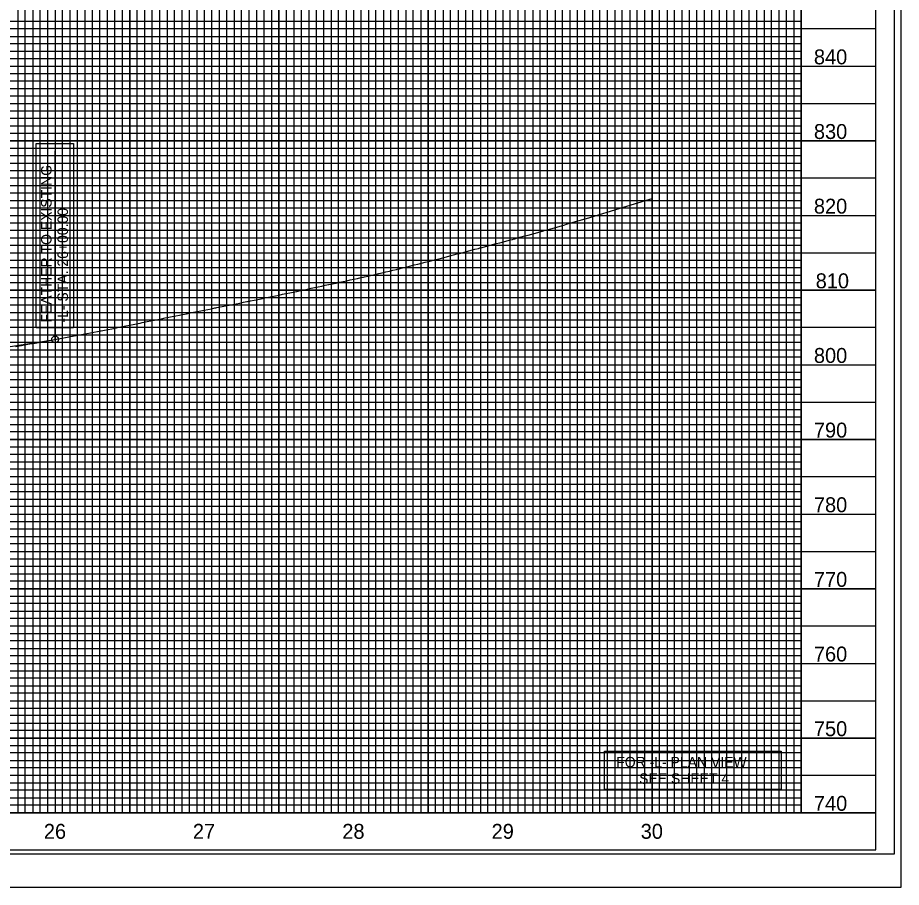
# Model space of a CAD drawing. Extents: x 573566 to 575250, y -53414 to -52314.
# Drawn here: x 574658 to 575250, y -53414 to -52832 of the extents above; entities that cross this region are included whole.
import ezdxf

# ---------------------------------------------------------------- set-up
doc = ezdxf.new("R2010")
doc.units = 0
for name, color, linetype in [('Exist Vertical Profile Ground Line', 7, 'Continuous'), ('Exist Vertical Profile Horizontal Axis Label Major', 7, 'Continuous'), ('Exist Vertical Profile Vertical Axis Label', 7, 'Continuous'), ('Prop Grid Mask', 7, 'Continuous'), ('Prop PFL Text', 7, 'Continuous'), ('Prop Vertical Profile Curve Label', 7, 'Continuous'), ('Prop Vertical Profile Grade', 7, 'Continuous'), ('Prop VPI Label', 7, 'Continuous'), ('Sheet Cutting Line CELL', 7, 'Continuous'), ('Sheet DOT Grid CELL', 7, 'Continuous'), ('Sheet Layout Profile Border', 7, 'Continuous'), ('Sheet Plot Border Inside CELL', 7, 'Continuous'), ('Sheet Plot Border Outside CELL', 7, 'Continuous'), ('Sheet Profile CELL', 7, 'Continuous'), ('Sheet Profile Grid Major CELL', 7, 'Continuous'), ('Sheet Profile Grid Middle CELL', 7, 'Continuous'), ('Sheet Profile Grid Minor CELL', 7, 'Continuous')]:
    doc.layers.add(name, color=color, linetype=linetype)

msp = doc.modelspace()

# ---------------------------------------------------------------- linework, layer by layer
at = {"layer": 'Exist Vertical Profile Ground Line'}
for points in [[(574993.19, -52979.11), (574995.57, -52978.44), (574997.96, -52977.78), (575000.34, -52977.12), (575002.73, -52976.45), (575005.11, -52975.79), (575007.5, -52975.13), (575009.88, -52974.46), (575011.7, -52973.96), (575012.27, -52973.83), (575013.35, -52973.58), (575014.65, -52973.26), (575014.87, -52973.21), (575017.04, -52972.56), (575019.43, -52971.86), (575021.81, -52971.15), (575024.2, -52970.44), (575026.58, -52969.74), (575028.97, -52969.03), (575038.41, -52966.21), (575039.27, -52965.96), (575064.24, -52958.52), (575081.08, -52953.28), (575083.31, -52952.59)], [(574802.36, -53023.62), (574804.75, -53023.14), (574807.13, -53022.67), (574809.52, -53022.19), (574811.9, -53021.72), (574812.28, -53021.65), (574812.87, -53021.53), (574813.48, -53021.43), (574813.76, -53021.36), (574814.29, -53021.25), (574816.67, -53020.76), (574819.06, -53020.27), (574821.45, -53019.78), (574823.83, -53019.28), (574826.22, -53018.79), (574828.6, -53018.3), (574830.99, -53017.82), (574833.37, -53017.33), (574835.76, -53016.84), (574838.03, -53016.37), (574838.14, -53016.35), (574840.53, -53015.85), (574842.91, -53015.36), (574842.93, -53015.36), (574845.3, -53014.85), (574847.68, -53014.35), (574850.07, -53013.84), (574852.45, -53013.34), (574854.84, -53012.83), (574857.23, -53012.33), (574859.61, -53011.83), (574862, -53011.32), (574864.38, -53010.82), (574866.59, -53010.35), (574866.77, -53010.32), (574869.15, -53009.8), (574871.54, -53009.28), (574873.92, -53008.77), (574876.31, -53008.25), (574878.69, -53007.74), (574881.08, -53007.22), (574883.46, -53006.71), (574885.85, -53006.19), (574888.23, -53005.68), (574889.31, -53005.45), (574889.52, -53005.43), (574889.95, -53005.3), (574890.62, -53005.15), (574893, -53004.59), (574895.39, -53004.04), (574897.78, -53003.49), (574900.16, -53002.93), (574902.55, -53002.38), (574904.93, -53001.83), (574907.32, -53001.27), (574909.7, -53000.72), (574912.09, -53000.17), (574912.45, -53000.09), (574913.97, -52999.72), (574914.47, -52999.59), (574916.86, -52998.99), (574919.24, -52998.39), (574921.63, -52997.79), (574924.01, -52997.19), (574926.4, -52996.6), (574928.78, -52996), (574931.17, -52995.4), (574933.3, -52994.87), (574933.55, -52994.81), (574935.19, -52994.41), (574935.94, -52994.22), (574938.33, -52993.59), (574940.71, -52992.97), (574943.1, -52992.34), (574945.48, -52991.72), (574947.87, -52991.09), (574950.25, -52990.47), (574952.64, -52989.84), (574954.31, -52989.41), (574955.02, -52989.23), (574955.19, -52989.18), (574957.41, -52988.6), (574959.79, -52987.96), (574962.18, -52987.33), (574964.56, -52986.69), (574966.95, -52986.06), (574967.87, -52985.82), (574969.33, -52985.42), (574969.36, -52985.42), (574971.72, -52984.79), (574974.1, -52984.16), (574976.49, -52983.53), (574978.88, -52982.91), (574981.26, -52982.28), (574983.65, -52981.65), (574986.03, -52981.02), (574988.42, -52980.4), (574989.75, -52980.05), (574990.8, -52979.77), (574991.32, -52979.63), (574993.19, -52979.11)], [(574656.86, -53051.82), (574659.25, -53051.39), (574660.86, -53051.1), (574661.63, -53050.97), (574662.95, -53050.75), (574664.02, -53050.56), (574666.4, -53050.12), (574668.79, -53049.69), (574671.17, -53049.26), (574673.56, -53048.82), (574675.94, -53048.39), (574678.33, -53047.96), (574680.71, -53047.53), (574683.1, -53047.1), (574685.48, -53046.67), (574686.81, -53046.44), (574687.86, -53046.24), (574687.87, -53046.24), (574690.25, -53045.79), (574692.64, -53045.34), (574695.02, -53044.89), (574697.41, -53044.44), (574699.8, -53044), (574702.18, -53043.55), (574704.57, -53043.1), (574706.95, -53042.66), (574709.34, -53042.22), (574711.72, -53041.77), (574712.99, -53041.54), (574713.03, -53041.53), (574713.08, -53041.52), (574713.66, -53041.4), (574714.11, -53041.31), (574716.49, -53040.84), (574718.88, -53040.36), (574721.26, -53039.88), (574723.65, -53039.41), (574726.03, -53038.93), (574728.42, -53038.46), (574730.8, -53037.98), (574733.19, -53037.51), (574735.57, -53037.03), (574737.96, -53036.56), (574740.16, -53036.12), (574740.35, -53036.08), (574741.62, -53035.82), (574742.73, -53035.6), (574745.12, -53035.11), (574747.5, -53034.63), (574749.89, -53034.14), (574752.27, -53033.66), (574754.66, -53033.18), (574757.04, -53032.69), (574759.43, -53032.21), (574761.81, -53031.73), (574764.2, -53031.25), (574766.58, -53030.77), (574767.58, -53030.57), (574768.97, -53030.29), (574771.35, -53029.81), (574773.74, -53029.34), (574776.12, -53028.86), (574778.51, -53028.38), (574780.9, -53027.91), (574783.28, -53027.43), (574785.67, -53026.96), (574788.05, -53026.49), (574788.18, -53026.46), (574790.44, -53026), (574791.05, -53025.88), (574791.64, -53025.76), (574792.82, -53025.52), (574795.21, -53025.04), (574797.59, -53024.57), (574799.98, -53024.09), (574802.36, -53023.62)]]:
    msp.add_lwpolyline(points, dxfattribs=at)
at = {"layer": 'Prop Grid Mask'}
for points in [[(574695.68, -53039.36), (574670.64, -53039.36), (574670.64, -52915.83), (574695.68, -52915.83)], [(575051.32, -53322.74), (575169.9, -53322.74), (575169.9, -53348.63), (575051.32, -53348.63)]]:
    msp.add_lwpolyline(points, close=True, dxfattribs=at)
at = {"layer": 'Prop Vertical Profile Curve Label'}
msp.add_circle((574683.31, -53047.03), 2.25, dxfattribs=at)
at = {"layer": 'Prop Vertical Profile Grade'}
msp.add_line((574633.31, -53055.05), (574683.31, -53047.03), dxfattribs=at)
at = {"layer": 'Prop VPI Label'}
msp.add_line((574683.31, -53047.03), (574683.31, -52920.7), dxfattribs=at)
at = {"layer": 'Sheet Cutting Line CELL'}
msp.add_line((573566.31, -53414.05), (575250.31, -53414.05), dxfattribs=at)
at = {"layer": 'Sheet DOT Grid CELL'}
for p, q in [((574683.31, -52339.05), (574683.31, -53364.05)), ((574733.31, -52339.05), (574733.31, -53364.05)), ((574783.31, -52339.05), (574783.31, -53364.05)), ((574833.31, -52339.05), (574833.31, -53364.05)), ((574883.31, -52339.05), (574883.31, -53364.05)), ((574933.31, -52339.05), (574933.31, -53364.05)), ((574983.31, -52339.05), (574983.31, -53364.05)), ((575033.31, -53364.05), (575033.31, -52476.6)), ((575083.31, -53364.05), (575083.31, -52476.6)), ((575133.31, -53364.05), (575133.31, -52476.6)), ((575183.31, -53364.05), (575183.31, -52476.6)), ((573733.31, -52864.05), (575233.31, -52864.05)), ((573733.31, -52914.05), (575233.31, -52914.05)), ((573733.31, -52964.05), (575233.31, -52964.05)), ((573733.31, -53014.05), (575233.31, -53014.05)), ((573733.31, -53064.05), (575233.31, -53064.05)), ((573733.31, -53114.05), (575233.31, -53114.05)), ((573733.31, -53164.05), (575233.31, -53164.05)), ((573733.31, -53214.05), (575233.31, -53214.05)), ((573733.31, -53264.05), (575233.31, -53264.05)), ((573733.31, -53314.05), (575233.31, -53314.05))]:
    msp.add_line(p, q, dxfattribs=at)
at = {"layer": 'Sheet Layout Profile Border'}
msp.add_lwpolyline([(573783.31, -52339.05), (573783.31, -53364.05), (575183.31, -53364.05), (575183.31, -52476.6), (575033.26, -52476.6), (575033.26, -52339.05)], close=True, dxfattribs=at)
at = {"layer": 'Sheet Plot Border Inside CELL'}
msp.add_lwpolyline([(575245.81, -52336.5), (573579.31, -52336.5), (573579.31, -53391.6), (575245.81, -53391.6)], close=True, dxfattribs=at)
at = {"layer": 'Sheet Plot Border Outside CELL'}
msp.add_lwpolyline([(575250.31, -52314.05), (573566.31, -52314.05), (573566.31, -53414.05), (575250.31, -53414.05)], close=True, dxfattribs=at)
at = {"layer": 'Sheet Profile CELL'}
msp.add_line((575233.31, -53364.05), (573733.31, -53364.05), dxfattribs=at)
msp.add_lwpolyline([(575233.31, -52339.05), (573733.31, -52339.05), (573733.31, -53389.05), (575233.31, -53389.05)], close=True, dxfattribs=at)
at = {"layer": 'Sheet Profile Grid Major CELL'}
for points in [[(574633.31, -52339.05), (574683.31, -52339.05), (574683.31, -53364.05), (574733.31, -53364.05), (574733.31, -52339.05), (574783.31, -52339.05), (574783.31, -53364.05), (574833.31, -53364.05), (574833.31, -52339.05), (574883.31, -52339.05), (574883.31, -53364.05), (574933.31, -53364.05), (574933.31, -52339.05), (574983.31, -52339.05), (574983.31, -53364.05), (575033.31, -53364.05), (575033.31, -52339.05), (575059.61, -52339.05)], [(575083.31, -52476.6), (575083.31, -53364.05), (575133.31, -53364.05), (575133.31, -52476.6)], [(575183.31, -52476.6), (575183.31, -53364.05), (575233.31, -53364.05)], [(575233.31, -52914.05), (573733.31, -52914.05), (573733.31, -52864.05), (575233.31, -52864.05)], [(575233.31, -53014.05), (573733.31, -53014.05), (573733.31, -52964.05), (575233.31, -52964.05)], [(575233.31, -53114.05), (573733.31, -53114.05), (573733.31, -53064.05), (575233.31, -53064.05)], [(575233.31, -53214.05), (573733.31, -53214.05), (573733.31, -53164.05), (575233.31, -53164.05)], [(575233.31, -53314.05), (573733.31, -53314.05), (573733.31, -53264.05), (575233.31, -53264.05)]]:
    msp.add_lwpolyline(points, dxfattribs=at)
at = {"layer": 'Sheet Profile Grid Middle CELL'}
for points in [[(574608.31, -52339.05), (574658.31, -52339.05), (574658.31, -53364.05), (574708.31, -53364.05), (574708.31, -52339.05), (574758.31, -52339.05), (574758.31, -53364.05), (574808.31, -53364.05), (574808.31, -52339.05), (574858.31, -52339.05), (574858.31, -53364.05), (574908.31, -53364.05), (574908.31, -52339.05), (574958.31, -52339.05), (574958.31, -53364.05), (575008.31, -53364.05), (575008.31, -52339.05)], [(575058.31, -52476.6), (575058.31, -53364.05), (575108.31, -53364.05), (575108.31, -52476.6)], [(575158.31, -52476.6), (575158.31, -53364.05)], [(575233.31, -52839.05), (573733.31, -52839.05), (573733.31, -52889.05), (575233.31, -52889.05)], [(575233.31, -52939.05), (573733.31, -52939.05), (573733.31, -52989.05), (575233.31, -52989.05)], [(575233.31, -53039.05), (573733.31, -53039.05), (573733.31, -53089.05), (575233.31, -53089.05)], [(575233.31, -53139.05), (573733.31, -53139.05), (573733.31, -53189.05), (575233.31, -53189.05)], [(575233.31, -53239.05), (573733.31, -53239.05), (573733.31, -53289.05), (575233.31, -53289.05)], [(575233.31, -53339.05), (573733.31, -53339.05)]]:
    msp.add_lwpolyline(points, dxfattribs=at)
at = {"layer": 'Sheet Profile Grid Minor CELL'}
for points in [[(574653.31, -53364.05), (574663.31, -53364.05), (574663.31, -52339.05)], [(574668.31, -52339.05), (574668.31, -53364.05), (574673.31, -53364.05), (574673.31, -52339.05)], [(574678.31, -52339.05), (574678.31, -53364.05), (574688.31, -53364.05), (574688.31, -52339.05)], [(574693.31, -52339.05), (574693.31, -53364.05), (574698.31, -53364.05), (574698.31, -52339.05)], [(574703.31, -52339.05), (574703.31, -53364.05), (574713.31, -53364.05), (574713.31, -52339.05)], [(574718.31, -52339.05), (574718.31, -53364.05), (574723.31, -53364.05), (574723.31, -52339.05)], [(574728.31, -52339.05), (574728.31, -53364.05), (574738.31, -53364.05), (574738.31, -52339.05)], [(574743.31, -52339.05), (574743.31, -53364.05), (574748.31, -53364.05), (574748.31, -52339.05)], [(574753.31, -52339.05), (574753.31, -53364.05), (574763.31, -53364.05), (574763.31, -52339.05)], [(574768.31, -52339.05), (574768.31, -53364.05), (574773.31, -53364.05), (574773.31, -52339.05)], [(574778.31, -52339.05), (574778.31, -53364.05), (574788.31, -53364.05), (574788.31, -52339.05)], [(574793.31, -52339.05), (574793.31, -53364.05), (574798.31, -53364.05), (574798.31, -52339.05)], [(574803.31, -52339.05), (574803.31, -53364.05)], [(574803.31, -53364.05), (574813.31, -53364.05), (574813.31, -52339.05)], [(574818.31, -52339.05), (574818.31, -53364.05), (574823.31, -53364.05), (574823.31, -52339.05)], [(574828.31, -52339.05), (574828.31, -53364.05), (574838.31, -53364.05), (574838.31, -52339.05)], [(574843.31, -52339.05), (574843.31, -53364.05), (574848.31, -53364.05), (574848.31, -52339.05)], [(574853.31, -52339.05), (574853.31, -53364.05), (574863.31, -53364.05), (574863.31, -52339.05)], [(574868.31, -52339.05), (574868.31, -53364.05), (574873.31, -53364.05), (574873.31, -52339.05)], [(574878.31, -52339.05), (574878.31, -53364.05), (574888.31, -53364.05), (574888.31, -52339.05)], [(574893.31, -52339.05), (574893.31, -53364.05), (574898.31, -53364.05), (574898.31, -52339.05)], [(574903.31, -52339.05), (574903.31, -53364.05), (574913.31, -53364.05), (574913.31, -52339.05)], [(574918.31, -52339.05), (574918.31, -53364.05), (574923.31, -53364.05), (574923.31, -52339.05)], [(574928.31, -52339.05), (574928.31, -53364.05), (574938.31, -53364.05), (574938.31, -52339.05)], [(574943.31, -52339.05), (574943.31, -53364.05), (574948.31, -53364.05), (574948.31, -52339.05)], [(574953.31, -52339.05), (574953.31, -53364.05), (574963.31, -53364.05), (574963.31, -52339.05)], [(574968.31, -52339.05), (574968.31, -53364.05), (574973.31, -53364.05), (574973.31, -52339.05)], [(574978.31, -52339.05), (574978.31, -53364.05), (574988.31, -53364.05), (574988.31, -52339.05)], [(574993.31, -52339.05), (574993.31, -53364.05), (574998.31, -53364.05), (574998.31, -52339.05)], [(575003.31, -52339.05), (575003.31, -53364.05), (575013.31, -53364.05), (575013.31, -52339.05)], [(575018.31, -52339.05), (575018.31, -53364.05), (575023.31, -53364.05), (575023.31, -52339.05)], [(575028.31, -52339.05), (575028.31, -53364.05), (575038.31, -53364.05), (575038.31, -52476.6)], [(575043.31, -52476.6), (575043.31, -53364.05), (575048.31, -53364.05), (575048.31, -52476.6)], [(575053.31, -52476.6), (575053.31, -53364.05), (575063.31, -53364.05), (575063.31, -52476.6)], [(575068.31, -52476.6), (575068.31, -53364.05), (575073.31, -53364.05), (575073.31, -52476.6)], [(575078.31, -52476.6), (575078.31, -53364.05), (575088.31, -53364.05), (575088.31, -52476.6)], [(575093.31, -52476.6), (575093.31, -53364.05), (575098.31, -53364.05), (575098.31, -52476.6)], [(575103.31, -52476.6), (575103.31, -53364.05), (575113.31, -53364.05), (575113.31, -52476.6)], [(575118.31, -52476.6), (575118.31, -53364.05)], [(575118.31, -53364.05), (575123.31, -53364.05), (575123.31, -52476.6)], [(575128.31, -52476.6), (575128.31, -53364.05), (575138.31, -53364.05), (575138.31, -52476.6)], [(575143.31, -52476.6), (575143.31, -53364.05), (575148.31, -53364.05), (575148.31, -52476.6)], [(575153.31, -52476.6), (575153.31, -53364.05), (575163.31, -53364.05), (575163.31, -52476.6)], [(575168.31, -52476.6), (575168.31, -53364.05), (575173.31, -53364.05), (575173.31, -52476.6)], [(575178.31, -52476.6), (575178.31, -53364.05), (575188.31, -53364.05)], [(575183.31, -52834.05), (573783.31, -52834.05), (573783.31, -52844.05), (575183.31, -52844.05)], [(575183.31, -52849.05), (573783.31, -52849.05), (573783.31, -52854.05), (575183.31, -52854.05)], [(575183.31, -52859.05), (573783.31, -52859.05)], [(573783.31, -52869.05), (575183.31, -52869.05)], [(575183.31, -52874.05), (573783.31, -52874.05), (573783.31, -52879.05), (575183.31, -52879.05)], [(575183.31, -52884.05), (573783.31, -52884.05), (573783.31, -52894.05), (575183.31, -52894.05)], [(575183.31, -52899.05), (573783.31, -52899.05), (573783.31, -52904.05), (575183.31, -52904.05)], [(575183.31, -52909.05), (573783.31, -52909.05), (573783.31, -52919.05), (575183.31, -52919.05)], [(575183.31, -52924.05), (573783.31, -52924.05), (573783.31, -52929.05), (575183.31, -52929.05)], [(575183.31, -52934.05), (573783.31, -52934.05), (573783.31, -52944.05), (575183.31, -52944.05)], [(575183.31, -52949.05), (573783.31, -52949.05), (573783.31, -52954.05), (575183.31, -52954.05)], [(575183.31, -52959.05), (573783.31, -52959.05), (573783.31, -52969.05), (575183.31, -52969.05)], [(575183.31, -52974.05), (573783.31, -52974.05), (573783.31, -52979.05), (575183.31, -52979.05)], [(575183.31, -52984.05), (573783.31, -52984.05), (573783.31, -52994.05), (575183.31, -52994.05)], [(575183.31, -52999.05), (573783.31, -52999.05), (573783.31, -53004.05), (575183.31, -53004.05)], [(575183.31, -53009.05), (573783.31, -53009.05), (573783.31, -53019.05), (575183.31, -53019.05)], [(575183.31, -53024.05), (573783.31, -53024.05), (573783.31, -53029.05), (575183.31, -53029.05)], [(575183.31, -53034.05), (573783.31, -53034.05), (573783.31, -53044.05), (575183.31, -53044.05)], [(575183.31, -53049.05), (573783.31, -53049.05), (573783.31, -53054.05), (575183.31, -53054.05)], [(575183.31, -53059.05), (573783.31, -53059.05), (573783.31, -53069.05), (575183.31, -53069.05)], [(575183.31, -53074.05), (573783.31, -53074.05), (573783.31, -53079.05), (575183.31, -53079.05)], [(575183.31, -53084.05), (573783.31, -53084.05), (573783.31, -53094.05), (575183.31, -53094.05)], [(575183.31, -53099.05), (573783.31, -53099.05), (573783.31, -53104.05), (575183.31, -53104.05)], [(575183.31, -53109.05), (573783.31, -53109.05), (573783.31, -53119.05), (575183.31, -53119.05)], [(575183.31, -53124.05), (573783.31, -53124.05), (573783.31, -53129.05), (575183.31, -53129.05)], [(575183.31, -53134.05), (573783.31, -53134.05), (573783.31, -53144.05), (575183.31, -53144.05)], [(575183.31, -53149.05), (573783.31, -53149.05), (573783.31, -53154.05), (575183.31, -53154.05)], [(575183.31, -53159.05), (573783.31, -53159.05)], [(573783.31, -53169.05), (575183.31, -53169.05)], [(575183.31, -53174.05), (573783.31, -53174.05), (573783.31, -53179.05), (575183.31, -53179.05)], [(575183.31, -53184.05), (573783.31, -53184.05)], [(573783.31, -53194.05), (575183.31, -53194.05)], [(575183.31, -53199.05), (573783.31, -53199.05), (573783.31, -53204.05), (575183.31, -53204.05)], [(575183.31, -53209.05), (573783.31, -53209.05), (573783.31, -53219.05), (575183.31, -53219.05)], [(575183.31, -53224.05), (573783.31, -53224.05), (573783.31, -53229.05), (575183.31, -53229.05)], [(575183.31, -53234.05), (573783.31, -53234.05), (573783.31, -53244.05), (575183.31, -53244.05)], [(575183.31, -53249.05), (573783.31, -53249.05), (573783.31, -53254.05), (575183.31, -53254.05)], [(575183.31, -53259.05), (573783.31, -53259.05), (573783.31, -53269.05), (575183.31, -53269.05)], [(575183.31, -53274.05), (573783.31, -53274.05), (573783.31, -53279.05), (575183.31, -53279.05)], [(575183.31, -53284.05), (573783.31, -53284.05), (573783.31, -53294.05), (575183.31, -53294.05)], [(575183.31, -53299.05), (573783.31, -53299.05), (573783.31, -53304.05), (575183.31, -53304.05)], [(575183.31, -53309.05), (573783.31, -53309.05), (573783.31, -53319.05), (575183.31, -53319.05)], [(575183.31, -53324.05), (573783.31, -53324.05), (573783.31, -53329.05), (575183.31, -53329.05)], [(575183.31, -53334.05), (573783.31, -53334.05), (573783.31, -53344.05), (575183.31, -53344.05)], [(575183.31, -53349.05), (573783.31, -53349.05), (573783.31, -53354.05), (575183.31, -53354.05)], [(575183.31, -53359.05), (573783.31, -53359.05)]]:
    msp.add_lwpolyline(points, dxfattribs=at)

# ---------------------------------------------------------------- texts
at = {"layer": 'Exist Vertical Profile Horizontal Axis Label Major'}
for s, p in [('26', (574675.79, -53381.55)), ('27', (574775.65, -53381.55)), ('28', (574875.78, -53381.55)), ('29', (574975.82, -53381.55)), ('30', (575075.69, -53381.55))]:
    msp.add_text(s, height=10, dxfattribs=at).set_placement(p)
at = {"layer": 'Exist Vertical Profile Vertical Axis Label'}
for s, p in [('840', (575191.74, -52862.8)), ('830', (575191.74, -52912.8)), ('820', (575191.74, -52962.8)), ('810', (575192.94, -53012.8)), ('800', (575191.74, -53062.8)), ('790', (575191.74, -53112.8)), ('780', (575191.74, -53162.8)), ('770', (575191.74, -53212.8)), ('760', (575191.74, -53262.8)), ('750', (575191.74, -53312.8)), ('740', (575191.74, -53362.8))]:
    msp.add_text(s, height=10, dxfattribs=at).set_placement(p)
at = {"layer": 'Prop PFL Text'}
for s, p in [('FOR -L- PLAN VIEW', (575059.3, -53333.68)), ('SEE SHEET 4', (575074.62, -53344.68))]:
    msp.add_text(s, height=7, dxfattribs=at).set_placement(p)
at = {"layer": 'Prop VPI Label'}
for s, p in [('FEATHER TO EXISTING', (574680.95, -53035.77)), ('-L- STA. 26+00.00', (574691.95, -53035.77))]:
    msp.add_text(s, height=7, rotation=90, dxfattribs=at).set_placement(p)

doc.saveas('drawing.dxf')
